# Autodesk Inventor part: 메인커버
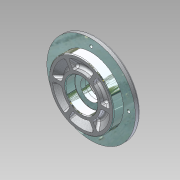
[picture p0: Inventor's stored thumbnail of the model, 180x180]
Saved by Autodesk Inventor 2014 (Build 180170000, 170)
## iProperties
Manager: KYOUNG IL JANG
Company: 한국ATC센터
Created: 2012-10
Part Number: 메인커버
Document SubType Name: Modeling
Density: 1 g/cm^3
Checked By: KYOUNG IL JANG
Vendor: CBT Solutions
Designer: KYOUNG IL JANG
Material: Generic
Appearance: _시험_알루미늄 표면거칠기
Author: KYOUNG IL JANG
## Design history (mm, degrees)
revolve "회전1" stored, may be unused: angle "d17" = 90 deg
feature "리브1" dims "d18" = 5, "d19" = 1, "d20" = 0
fillet "모깎기1" dims "d21" = 3
fillet "모깎기2" dims "d25" = 3, "d26" = 0.3
chamfer "모따기1" distance "d27" = 1; stored, may be unused: second distance "d28" = 2, angle "d29" = 45 deg
sketch "스케치3"
  geometry: C1 r 2.067 at (55, 0) reference; C2 r 2.067 at (0, -55) reference; C3 r 2.067 at (-55, 0) reference; C4 r 2.067 at (0, 55) reference; 1 further point
hole "구멍1" sketch "스케치3" diameter "d30" = 4.5; stored, may be unused: countersink angle "d34" = 90 deg, drill point angle "d36" = 118 deg; dims "d31" = 6, "d32" = 8, "d33" = 4.4, "d35" = 8
node "솔리드1"
pattern_circular "원형 패턴1" dims angle "d23" = 360 deg
sketch "스케치1"
  geometry: L1 (0, 0)-(0, 28.5); L2 (0, 0)-(28.5, 0); L3 (28.5, 0)-(28.5, 4.726); L4 (28.5, 8)-(31.774, 8); L5 (32.966, 8)-(33.879, 7.234); L6 (42.5, 0)-(47.5, 0); L7 (47.5, 0)-(47.5, 14.5); L8 (47.5, 14.5)-(65, 14.5); L9 (65, 14.5)-(65, 22.5); L10 (65, 22.5)-(33.464, 22.5); L11 (33.464, 22.5)-(30, 28.5); L12 (30, 28.5)-(0, 28.5); L13 (28.5, 4.726)-(28.5, 8); L14 (31.774, 8)-(32.966, 8); L15 (33.879, 7.234)-(42.5, 0); L16 (23.5, 0)-(23.5, 14); L17 (23.5, 14)-(15, 14); L18 (15, 14)-(15, 20.5); L19 (15, 20.5)-(17.5, 20.5); L20 (17.5, 20.5)-(17.5, 28.5); A1 r 3.274 centre (31.774, 4.726) between (33.879, 7.234) and (28.5, 4.726)
  constraints: 40 end point, 11 parallel, 6 perpendicular, 6 tangent, 3 point on circle, 2 collinear, 2 point on line, 1 centre point, 1 vertical
  dimensions: "d1" = 130 diameter of L9 L1; "d2" = 95 diameter of L7 L1; "d3" = 57 diameter of L3 L1; "d4" = 5 distance of L6.start L6.end; "d5" = 14.5 distance between parallel lines of L8 L6; "d6" = 8 distance of L8.end L9.end; "d7" = 6 distance between parallel lines of L10 L12; "d8" = 8 distance of L2.end L4.start; "d9" = 140 deg angle of L6 L5; "d10" = 47 diameter of L16 L1; "d11" = 14 distance of L16.start L16.end; "d12" = 35 diameter of L20 L1; "d13" = 8 distance of L19.end L20.end; "d14" = 30 diameter of L18 L1; "d15" = 120 deg angle of L10 L11; "d16" = 60 diameter of L11.end L1
sketch "스케치2"
  geometry: L1 (28.5, 0)-(42.5, 0); 3 further points
  constraints: 2 end point, 2 horizontal alignment, 1 horizontal, 1 point on line, 2 other
node "참조1"
node "참조2"
node "참조3"
node "참조4"
